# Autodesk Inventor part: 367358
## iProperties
Created: 2006-08
Part Number: 367358
Material: 8.8 vz
Description: Senkschraube
Vendor: Autodesk Inc.
Document SubType Name: Modeling
Standard: DIN 7991
Designer: I.Baliuc
Standards Organization: DIN
Language: de-DE
Size Designation: M5 x 16
Categories: <MemberInstance Version="R10.0.0"><Categories><Category DisplayName="Schrauben" InternalName="e4da775c-781d-43d5-af7c-5136215cf5a6" Mnemonic="FSTN"><Category Di
Density: 7.85 g/cm^3
Mass: 2.94006 g
Surface Area: 4.19443 cm^2
Volume: 0.37453 cm^3
Abmessung: M5 x 16
Author: T.Messerschmitt
Comments: DIN 7991 - M5 x 16
Revision Number: 367358
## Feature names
1. Körper [Revolution]
2. Loch [Extrusion]
3. Fase1 [Chamfer]
